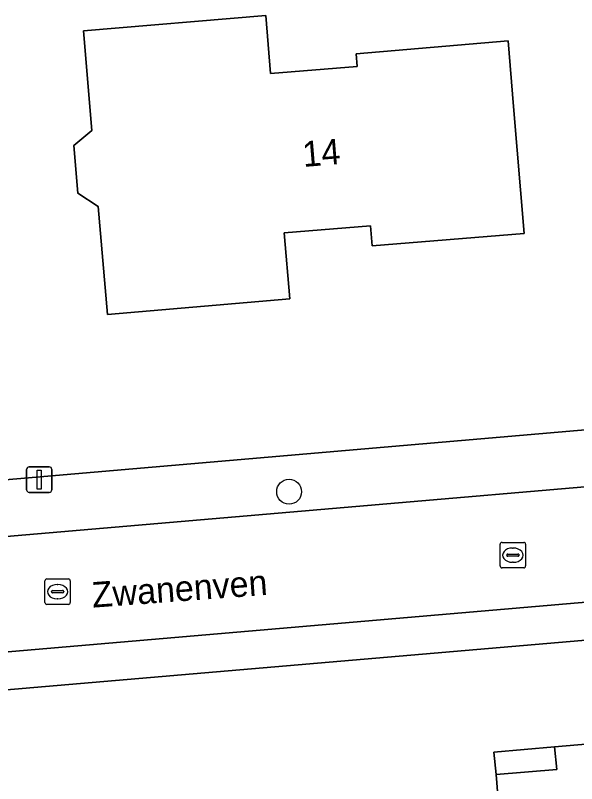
# Model space of a CAD drawing. Extents: x 163426 to 164192, y 380329 to 381641.
# Drawn here: x 164091.43 to 164113.49, y 381051.81 to 381081.98 of the extents above; entities that cross this region are included whole.
import ezdxf

# ---------------------------------------------------------------- set-up
doc = ezdxf.new("R2010")
doc.units = 0
for name, color, linetype in [('IMGEO_Boom', 7, 'Continuous'), ('IMGEO_Erf', 7, 'Continuous'), ('IMGEO_Kolk', 7, 'Continuous'), ('IMGEO_Lichtmast', 7, 'Continuous'), ('IMGEO_Openbare_ruimte_label', 7, 'Continuous'), ('IMGEO_Pand', 7, 'Continuous'), ('IMGEO_Pand_nummerreeks', 7, 'Continuous'), ('IMGEO_Pand_overbouw', 7, 'Continuous'), ('IMGEO_Rijbaan_lokaal_open', 7, 'Continuous'), ('IMGEO_Voetpad_open', 7, 'Continuous')]:
    doc.layers.add(name, color=color, linetype=linetype)

msp = doc.modelspace()

# ---------------------------------------------------------------- linework, layer by layer
at = {"layer": 'IMGEO_Boom'}
msp.add_circle((164102.189, 381063.272), 0.489, dxfattribs=at)
at = {"layer": 'IMGEO_Erf'}
for points in [[(164110.793, 381080.978), (164111.009, 381078.401), (164111.427, 381073.418), (164105.45, 381072.927), (164105.385, 381073.714), (164101.998, 381073.436), (164102.211, 381070.846), (164095.045, 381070.23), (164094.689, 381074.473), (164093.881, 381075.003), (164093.724, 381076.874), (164094.439, 381077.454), (164094.109, 381081.381), (164101.272, 381081.982), (164101.464, 381079.694), (164104.866, 381079.98), (164104.824, 381080.477)], [(164110.328, 381052.166), (164110.241, 381053.044), (164112.625, 381053.255), (164118.6, 381053.76), (164118.71, 381053.769), (164118.803, 381052.821), (164122.018, 381053.095), (164122.122, 381051.877), (164126.256, 381052.229), (164126.395, 381052.241), (164127.111, 381043.784), (164122.914, 381043.365), (164123.098, 381041.521), (164121.821, 381040.057), (164118.992, 381039.794), (164117.585, 381041.02), (164117.548, 381041.429), (164116.899, 381041.37), (164116.872, 381041.669), (164112.981, 381041.315), (164112.799, 381043.392), (164112.361, 381048.372), (164110.637, 381048.221)], [(164112.625, 381053.255), (164110.241, 381053.044), (164110.328, 381052.166), (164112.712, 381052.361)]]:
    msp.add_lwpolyline(points, close=True, dxfattribs=at)
for points in [[(164050.279, 381060.237), (164129.935, 381067.097)], [(164127.903, 381058.65), (164077.934, 381054.369), (164053.22, 381052.357), (164049.464, 381051.933)]]:
    msp.add_lwpolyline(points, dxfattribs=at)
at = {"layer": 'IMGEO_Kolk'}
for p, q in [((164110.483, 381060.357), (164110.483, 381061.209)), ((164110.558, 381061.283), (164111.41, 381061.283)), ((164111.484, 381061.209), (164111.484, 381060.357)), ((164110.971, 381061.063), (164110.996, 381061.063)), ((164110.742, 381060.777), (164110.742, 381060.789)), ((164111.18, 381060.74), (164110.782, 381060.74)), ((164110.785, 381060.826), (164111.183, 381060.826)), ((164111.226, 381060.789), (164111.226, 381060.777)), ((164111.41, 381060.283), (164110.558, 381060.283)), ((164110.994, 381060.503), (164110.969, 381060.503)), ((164092.588, 381058.921), (164092.588, 381059.773)), ((164092.663, 381059.847), (164093.515, 381059.847)), ((164093.589, 381059.773), (164093.589, 381058.921)), ((164092.89, 381059.39), (164093.288, 381059.39)), ((164093.076, 381059.627), (164093.101, 381059.627)), ((164092.847, 381059.341), (164092.847, 381059.353)), ((164093.285, 381059.304), (164092.887, 381059.304)), ((164093.099, 381059.067), (164093.074, 381059.067)), ((164093.331, 381059.353), (164093.331, 381059.341)), ((164093.515, 381058.847), (164092.663, 381058.847))]:
    msp.add_line(p, q, dxfattribs=at)
for points in [[(164110.483, 381060.357), (164110.483, 381061.209)], [(164110.558, 381061.283), (164111.41, 381061.283)], [(164111.484, 381061.209), (164111.484, 381060.357)], [(164111.41, 381060.283), (164110.558, 381060.283)], [(164092.588, 381058.921), (164092.588, 381059.773)], [(164092.663, 381059.847), (164093.515, 381059.847)], [(164093.589, 381059.773), (164093.589, 381058.921)], [(164093.515, 381058.847), (164092.663, 381058.847)]]:
    msp.add_lwpolyline(points, dxfattribs=at)
for centre, radius, start, end in [((164110.56, 381061.207), 0.0765, 91.552, 178.448), ((164110.56, 381061.207), 0.0765, 91.552, 178.448), ((164111.408, 381061.207), 0.0765, 1.552, 88.448), ((164111.408, 381061.207), 0.0765, 1.552, 88.448), ((164110.782, 381060.786), 0.0403, 85.8775, 175.7526), ((164110.779, 381060.776), 0.0366, 178.938, 274.7102), ((164111.183, 381060.783), 0.043, 264.8664, 352.4533), ((164111.187, 381060.788), 0.0386, 1.7309, 96.639), ((164110.56, 381060.359), 0.0765, 181.552, 268.448), ((164110.56, 381060.359), 0.0765, 181.552, 268.448), ((164111.408, 381060.359), 0.0765, 271.552, 358.448), ((164111.408, 381060.359), 0.0765, 271.552, 358.448), ((164092.665, 381059.771), 0.0765, 91.552, 178.448), ((164092.665, 381059.771), 0.0765, 91.552, 178.448), ((164093.513, 381059.771), 0.0765, 1.552, 88.448), ((164093.513, 381059.771), 0.0765, 1.552, 88.448), ((164092.887, 381059.35), 0.0403, 85.8775, 175.7526), ((164093.292, 381059.352), 0.0386, 1.7309, 96.639), ((164092.884, 381059.34), 0.0366, 178.938, 274.7102), ((164093.288, 381059.347), 0.043, 264.8664, 352.4533), ((164092.665, 381058.923), 0.0765, 181.552, 268.448), ((164092.665, 381058.923), 0.0765, 181.552, 268.448), ((164093.513, 381058.923), 0.0765, 271.552, 358.448), ((164093.513, 381058.923), 0.0765, 271.552, 358.448)]:
    msp.add_arc(centre, radius, start, end, dxfattribs=at)
for centre, major_axis, ratio, start_param, end_param in [((164110.97, 381060.783), (-0.387, 0.002), 0.722429, 4.712389, 7.853982), ((164110.995, 381060.783), (-0.39, 0.002), 0.717154, 1.570796, 4.712389), ((164093.075, 381059.347), (-0.387, 0.002), 0.722429, 4.712389, 7.853982), ((164093.1, 381059.347), (-0.39, 0.002), 0.717154, 1.570796, 4.712389)]:
    msp.add_ellipse(centre, major_axis=major_axis, ratio=ratio, start_param=start_param, end_param=end_param, dxfattribs=at)
at = {"layer": 'IMGEO_Lichtmast'}
for p, q in [((164091.971, 381064.249), (164092.761, 381064.249)), ((164092.761, 381064.249), (164091.971, 381064.249)), ((164091.871, 381063.349), (164091.871, 381064.149)), ((164091.871, 381064.149), (164091.871, 381063.349)), ((164092.861, 381064.149), (164092.861, 381063.349)), ((164092.861, 381063.349), (164092.861, 381064.149)), ((164092.761, 381063.249), (164091.971, 381063.249)), ((164091.971, 381063.249), (164092.761, 381063.249))]:
    msp.add_line(p, q, dxfattribs=at)
msp.add_lwpolyline([(164092.291, 381064.124), (164092.441, 381064.124), (164092.441, 381063.374), (164092.291, 381063.374), (164092.291, 381064.124)], dxfattribs=at)
for centre, start, end in [((164091.971, 381064.149), 90, 180), ((164091.971, 381064.149), 90, 180), ((164092.761, 381064.149), 0, 90), ((164092.761, 381064.149), 360, 90), ((164091.971, 381063.349), 180, 270), ((164091.971, 381063.349), 180, 270), ((164092.761, 381063.349), 270, 0), ((164092.761, 381063.349), 270, 0)]:
    msp.add_arc(centre, 0.1, start, end, dxfattribs=at)
at = {"layer": 'IMGEO_Pand'}
for points in [[(164111.009, 381078.401), (164110.793, 381080.978), (164104.824, 381080.477), (164104.866, 381079.98), (164101.464, 381079.694), (164101.272, 381081.982), (164094.109, 381081.381), (164094.439, 381077.454), (164093.724, 381076.874), (164093.881, 381075.003), (164094.689, 381074.473), (164095.045, 381070.23), (164102.211, 381070.846), (164101.998, 381073.436), (164105.385, 381073.714), (164105.45, 381072.927), (164111.427, 381073.418)], [(164110.328, 381052.166), (164110.637, 381048.221), (164112.361, 381048.372), (164112.799, 381043.392), (164112.981, 381041.315), (164116.872, 381041.669), (164116.899, 381041.37), (164117.548, 381041.429), (164117.585, 381041.02), (164118.992, 381039.794), (164121.821, 381040.057), (164123.098, 381041.521), (164122.914, 381043.365), (164127.111, 381043.784), (164126.395, 381052.241), (164126.256, 381052.229), (164122.122, 381051.877), (164122.018, 381053.095), (164118.803, 381052.821), (164118.71, 381053.769), (164118.6, 381053.76), (164112.625, 381053.255), (164112.712, 381052.361)]]:
    msp.add_lwpolyline(points, close=True, dxfattribs=at)
at = {"layer": 'IMGEO_Pand_overbouw'}
msp.add_lwpolyline([(164110.328, 381052.166), (164112.712, 381052.361), (164112.625, 381053.255), (164110.241, 381053.044)], close=True, dxfattribs=at)
at = {"layer": 'IMGEO_Rijbaan_lokaal_open'}
for points in [[(164130.134, 381064.866), (164050.175, 381058.005)], [(164050.427, 381053.487), (164131.078, 381060.415)]]:
    msp.add_lwpolyline(points, dxfattribs=at)
at = {"layer": 'IMGEO_Voetpad_open'}
for points in [[(164129.935, 381067.097), (164050.279, 381060.237)], [(164050.175, 381058.005), (164130.134, 381064.866)], [(164131.078, 381060.415), (164050.427, 381053.487)], [(164049.464, 381051.933), (164053.22, 381052.357), (164077.934, 381054.369), (164127.903, 381058.65), (164130.402, 381058.864)]]:
    msp.add_lwpolyline(points, dxfattribs=at)

# ---------------------------------------------------------------- texts
at = {"layer": 'IMGEO_Openbare_ruimte_label'}
msp.add_text('Zwanenven', height=1, rotation=4.1877, dxfattribs=at).set_placement((164094.471, 381058.72))
at = {"layer": 'IMGEO_Pand_nummerreeks'}
msp.add_text('14', height=1, rotation=4.6925, dxfattribs=at).set_placement((164102.752, 381076.027))

doc.saveas('drawing.dxf')
